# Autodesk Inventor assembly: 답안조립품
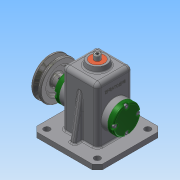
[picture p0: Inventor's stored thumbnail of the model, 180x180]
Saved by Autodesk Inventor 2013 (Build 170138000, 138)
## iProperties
Created: 2016-02
Part Number: 답안조립품
Document SubType Name: Assembly
Designer: Administrator
Author: Administrator
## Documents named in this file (16)
- C:\Users\Administrator\Desktop\460212V1019\답안조립품.iam
- C:\Users\Administrator\Desktop\460212V1019\1본체.ipt
- C:\Users\Administrator\Desktop\460212V1019\뒤커버.ipt
- C:\Users\Administrator\Desktop\460212V1019\앞커버.ipt
- C:\Users\Administrator\Desktop\460212V1019\베어링 12 x 32 x 10.ipt
- C:\Users\Administrator\Desktop\460212V1019\볼트 M4 x 12.ipt
- C:\Users\Administrator\Desktop\460212V1019\편심축.ipt
- C:\Users\Administrator\Desktop\460212V1019\슬라이드.ipt
- C:\Users\Administrator\Desktop\460212V1019\링크.ipt
- C:\Users\Administrator\Desktop\460212V1019\핀 5 x 18.ipt
- C:\Users\Administrator\Desktop\460212V1019\고정핀 1.2 x 10.ipt
- C:\Users\Administrator\Desktop\460212V1019\부시.ipt
- C:\Users\Administrator\Desktop\460212V1019\오일실 12 25 7.ipt
- C:\Users\Administrator\Desktop\460212V1019\V벨트풀리.ipt
- C:\Users\Administrator\Desktop\460212V1019\키 4 x 4 x 10.ipt
- C:\Users\Administrator\Desktop\460212V1019\멈춤나사 M3x8.ipt
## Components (12 placed, 5 different names)
1. 1본체:1
2. 핀 5 x 18:1
3. 고정핀 1.2 x 10:1
4. V벨트풀리:1
5. ISO 4762 M4 x 12:2
6. ISO 4762 M4 x 12:3
7. ISO 4762 M4 x 12:4
8. ISO 4762 M4 x 12:5
9. ISO 4762 M4 x 12:1
10. ISO 4762 M4 x 12:6
11. ISO 4762 M4 x 12:7
12. ISO 4762 M4 x 12:8
